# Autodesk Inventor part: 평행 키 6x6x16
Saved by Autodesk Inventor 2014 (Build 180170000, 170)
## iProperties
Created: 2026-04
Part Number: 평행 키 6x6x16
Material: 일반
Document SubType Name: Modeling
Designer: dg
Density: 1 g/cm^3
Appearance: 기본값
Author: dg
Author: jhkim
Description: 키 및 해당 키홈
Creation Date: 2026-03-27
Sending System: Autodesk Inventor 2026
Preprocessor: ST-DEVELOPER v20.1
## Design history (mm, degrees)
node "평행 키 6x6x161"
body "Solid1"
node "기준1"
